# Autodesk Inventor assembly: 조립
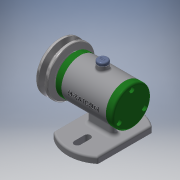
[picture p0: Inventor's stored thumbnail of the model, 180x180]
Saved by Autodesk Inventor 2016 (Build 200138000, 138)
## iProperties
Created: 2017-12
Part Number: 조립
Material: 일반
Document SubType Name: Assembly
Designer: 605-04
Author: 605-04
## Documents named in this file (13)
- C:\Users\605-04\Desktop\471207V1015\조립.iam
- C:\Users\605-04\Desktop\471207V1015\본체.ipt
- C:\Users\605-04\Desktop\471207V1015\축.ipt
- C:\Users\605-04\Desktop\471207V1015\뒤커버.ipt
- C:\Users\605-04\Desktop\471207V1015\베어링 15 x 32 x 9.ipt
- C:\Users\605-04\Desktop\471207V1015\앞커버.ipt
- C:\Users\605-04\Desktop\471207V1015\오일 실 15 25 7.ipt
- C:\Users\605-04\Desktop\471207V1015\V벨트풀리.ipt
- C:\Users\605-04\Desktop\471207V1015\키 3 x 3 x 12.ipt
- C:\Users\605-04\Desktop\471207V1015\고무캡.ipt
- C:\Users\605-04\Desktop\471207V1015\너트 M 8.ipt
- C:\Users\605-04\Desktop\471207V1015\스프링와셔 8.ipt
- C:\Users\605-04\Desktop\471207V1015\와셔 8x17.ipt
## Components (2 placed, 2 different names)
1. V벨트풀리:1 — 각도:2
2. 고무캡:1 — 각도:3
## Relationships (2: Angle 2)
- 각도:2 [Angle]: V벨트풀리:1
- 각도:3 [Angle]: 고무캡:1
